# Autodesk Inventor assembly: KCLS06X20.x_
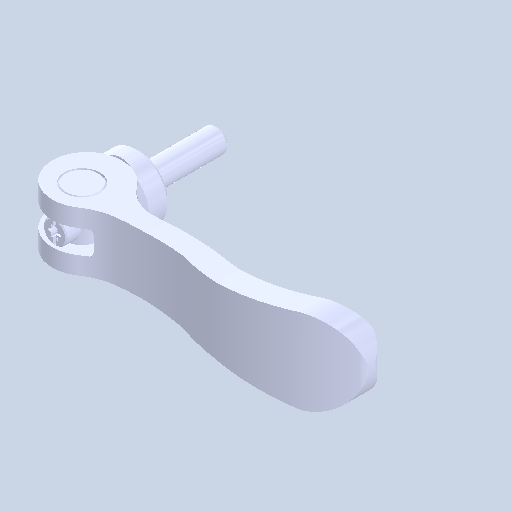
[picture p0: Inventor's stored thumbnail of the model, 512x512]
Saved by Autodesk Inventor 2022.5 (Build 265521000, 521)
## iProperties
Created: 2024-08
Part Number: KCLS06X20.x_
Document SubType Name: Assembly
Designer: ImaoCorp
Author: ImaoCorp
Sending System: SOLIDWORKS 2022-2022290
MC: AMD64
MC_MODEL: Intel64 Family 6 Model 60 Stepping 3, GenuineIntel
OS: Windows_NT
FRU: Parasolid Version 33.1, build 260,  4-25-2022
FORMAT: text
GUISE: transmit
KEY: FILEKCLS06X20.x_t
DATE: Thu Aug 29 10:54:51 2024
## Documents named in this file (5)
- Y:\5.更新分\2024年対応\1001_KCL\データ\kcls06x20\KCLS06X20.x_.iam
- Y:\5.更新分\2024年対応\1001_KCL\データ\kcls06x20\KCLS06X20_01.ipt
- Y:\5.更新分\2024年対応\1001_KCL\データ\kcls06x20\KCLS06X20_02.ipt
- Y:\5.更新分\2024年対応\1001_KCL\データ\kcls06x20\KCLS06X20_03.ipt
- Y:\5.更新分\2024年対応\1001_KCL\データ\kcls06x20\KCLS06X20_04.ipt
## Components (4 placed, 4 different names)
1. KCLS06X20_01
2. KCLS06X20_02
3. KCLS06X20_03
4. KCLS06X20_04
